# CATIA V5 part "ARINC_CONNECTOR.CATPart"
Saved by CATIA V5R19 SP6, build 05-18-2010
Part number: ARINC_CONNECTOR
Revision: --A
Publications: "Logical Termination.1", "Logical Pin.1", "BCP_A", "Point.3_generated(BCP1)", "Plane.6_generated(BCP1)", "BCP_B", "Point.2_generated(BCP2)", "BCP_C", "Point.1_generated(BCP3)", "CaCP", "Face_generated(CaCP)", "Axis_generated(CaCP)", "Face_generated(CaCP).1", "CCP", "Face_generated(CCP)", "Axis_generated(CCP)", "Face_generated(CCP).1", "InsertFrontFace", "InsertRearFace", "MasterKeywayAxis", "BaCP", "BaCPRPoint_generated(BaCP)", "BaCPCPlane_generated(BaCP)", "Face_generated(BaCP)", "Face_generated(BaCP).1", "Axis_generated(BaCP)"
Bounding box of the stored display mesh (mm): x 0 to 35.56, y -22.86 to 22.86, z -88.646 to 88.646
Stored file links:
  C:\Users\ajc8720\Documents\BOEING_WORK\0001-2CES\004-AP242\Boeing-Generic_Harness_R3\ARINC_CONNECTOR.CATPart
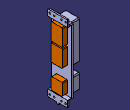
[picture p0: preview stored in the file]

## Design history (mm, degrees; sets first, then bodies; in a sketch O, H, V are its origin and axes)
Parameters
  PartNumber = "ARINC_CONNECTOR"
AxisSystem1 "MasterKeywayAxis": origin (0, 0, 0), X (1, 0, 0), Y (0, 1, 0), Z (0, 0, 1)
Set1 "EGF"
  Set2 "BCP"
    Point1 "BCPRPoint1": type OnSurface, Support start face of Pad4, Length 0, Direction (0, 0.1324, -0.9912)
    Plane1 "BCPPlane": type OffsetPt, RefPlane yz-plane, RefPoint Point1
  Set3 "BCP2"
    Point2 "BCPRPoint2": type OnSurface, Support start face of Pad4, Length 0, Direction (0, 0.4082, -0.9129)
  Set4 "BCP3"
    Point3 "BCPRPoint3": type OnSurface, Support start face of Pad4, Length 0, Direction (0, 0.0589, -0.9983)
  Set5 "CaCP"
    Point4 "CaCPRPoint": (18.923, 0, 0), in AxisSystem1
    Plane2 "CaCPCPlane": type OffsetPt, RefPlane face of Pad1 from Sketch1.L6, RefPoint Point4
  Set6 "CCP"
    Point5 "CCPRPoint": (18.923, 0, 0), in AxisSystem1
  Set7 "BaCP"
    Plane3 "BaCPCPlane": type Offset, RefPlane yz-plane, Offset 24.257
    Point6 "BaCPRPoint": type OnSurface, Support Plane3, Length 0, Direction (0, 0.9983, -0.058)
Set8 "ConstructionGeometry"
  Plane4: type Offset, RefPlane face of Pad1 from Sketch1.L9, Offset 6.35
  Plane5: type Offset, RefPlane xy-plane, Offset 29.21
  Plane6 "DatumCC": type Offset, RefPlane yz-plane, Offset 35.56
  Plane7: type Offset, RefPlane xy-plane, Offset 29.21
  Plane8: type Offset, RefPlane yz-plane, Offset 35.56
Body1 (main body)
  Sketch1 on zx-plane, origin (0, 0, 0), H (-1, 0, 0), V (0, 0, 1)
    line L1 (-24.257, 73.914) -> (-33.274, 73.914)
    line L2 (-33.274, 73.914) -> (-33.274, 88.646)
    line L3 (-33.274, 88.646) -> (-30.099, 88.646)
    line L4 (-30.099, 88.646) -> (-30.099, 76.454)
    line L5 (-30.099, 76.454) -> (-21.082, 76.454)
    line L6 (-21.082, 76.454) -> (-21.082, -72.898)
    line L7 (-21.082, -72.898) -> (-30.099, -72.898)
    point P8 (-30.099, -72.898)
    line L8 (-30.099, -72.898) -> (-30.099, -85.344)
    line L9 (-30.099, -85.344) -> (-33.274, -85.344)
    point P10 (-33.274, -85.344)
    line L10 (-33.274, -85.344) -> (-33.274, -70.358)
    line L11 (-33.274, -70.358) -> (-24.257, -70.358)
    line L12 (-24.257, -70.358) -> (-24.257, 73.914)
    distance L12 L6 = 3.175
    length L9 = 3.175
    distance L6 V = 21.082
    distance L7 L11 = 2.54
    distance L2 V = 33.274
    distance L3 L9 = 173.99
    distance L1 L5 = 2.54
    distance L9 L7 = 12.446
    distance H L9 = 85.344
    distance L9 L5 = 161.798
    horizontal: L1 H, L3 H, L5 H, L7 H, L9 H, L11 H
    vertical: L2 V, L4 V, L6 V, L8 V, L10 V, L12 V
    coincidence: P8 L4, P10 L2
  Pad1: profile Sketch1, direction (0, 1, 0), length 22.86, mirrored extent
  Sketch2 on face of Pad1 from Sketch1.L10, origin (33.274, 0, 0), H (0, 1, 0), V (0, 0, 1)
    point P1 (0, -86.995)
    line L1 (2.3622, -85.344) -> (2.3622, -88.646)
    line L2 (2.3622, -88.646) -> (-2.3622, -88.646)
    line L3 (-2.3622, -88.646) -> (-2.3622, -85.344)
    line L4 (-2.3622, -85.344) -> (2.3622, -85.344)
    reference projected line E1 (-41.402, -85.344) -> (41.402, -85.344) from edge [face of Pad1 from Sketch1.L9 | face of Pad1 from Sketch1.L10]
    length L1 = 3.302
    length L2 = 4.7244
    coincidence: P1 V, L4 E1
    vertical: L1 V, L3 V
    horizontal: L2 H, L4 H
    equidistance: L1 L3 P1, L2 L4 P1
  Pad2: profile Sketch2, direction (-1, 0, 0), length 3.175
  Sketch3 on face of Pad1 from Sketch1.L6, origin (21.082, 0, 0), H (0, -1, 0), V (0, 0, 1)
    point P1 (0, 29.2227)
    line L1 (16.3703, 70.6882) -> (16.3703, -12.2428)
    line L2 (14.2875, -14.3256) -> (-14.2875, -14.3256)
    line L3 (-16.3703, -12.2428) -> (-16.3703, 70.6882)
    line L4 (-14.2875, 72.771) -> (14.2875, 72.771)
    point P2 (0, -52.6923)
    line L5 (16.3703, -37.7952) -> (16.3703, -67.5894)
    line L6 (14.2875, -69.6722) -> (-14.2875, -69.6722)
    line L7 (-16.3703, -67.5894) -> (-16.3703, -37.7952)
    line L8 (-14.2875, -35.7124) -> (14.2875, -35.7124)
    reference projected line E1 (2.3622, -88.646) -> (-2.3622, -88.646) from edge [end face of Pad2 | face of Pad2 from Sketch2.L2]
    arc A1 centre (14.2875, 70.6882) radius 2.0828 from (14.2875, 72.771) to (16.3703, 70.6882) cw
    arc A2 centre (-14.2875, 70.6882) radius 2.0828 from (-14.2875, 72.771) to (-16.3703, 70.6882) ccw
    arc A3 centre (-14.2875, -12.2428) radius 2.0828 from (-16.3703, -12.2428) to (-14.2875, -14.3256) ccw
    arc A4 centre (14.2875, -12.2428) radius 2.0828 from (14.2875, -14.3256) to (16.3703, -12.2428) ccw
    arc A5 centre (14.2875, -37.7952) radius 2.0828 from (14.2875, -35.7124) to (16.3703, -37.7952) cw
    arc A6 centre (-14.2875, -37.7952) radius 2.0828 from (-14.2875, -35.7124) to (-16.3703, -37.7952) ccw
    arc A7 centre (-14.2875, -67.5894) radius 2.0828 from (-16.3703, -67.5894) to (-14.2875, -69.6722) ccw
    arc A8 centre (14.2875, -67.5894) radius 2.0828 from (14.2875, -69.6722) to (16.3703, -67.5894) ccw
    distance P1 P2 = 81.915
    distance L1 L3 = 32.7406
    distance L8 L6 = 33.9598
    distance L2 L4 = 87.0966
    distance E1 L4 = 161.417
    radius A1 = 2.0828
    radius A2 = 2.0828
    radius A3 = 2.0828
    radius A4 = 2.0828
    radius A5 = 2.0828
    radius A6 = 2.0828
    radius A7 = 2.0828
    radius A8 = 2.0828
    coincidence: P1 V, P2 V, L5 L1
    vertical: L1 V, L3 V, L5 V, L7 V
    horizontal: L2 H, L4 H, L6 H, L8 H
    equidistance: L1 L3 P1, L2 L4 P1, L5 L7 P2, L6 L8 P2
    tangency: A1 L4, A1 L1, A2 L4, A2 L3, A3 L3, A3 L2, A4 L2, A4 L1, A5 L8, A5 L5, A6 L8, A6 L7, A7 L7, A7 L6, A8 L6, A8 L5
  Pad3: profile Sketch3, direction (-1, 0, 0), length 21.082
  Sketch4 on end face of Pad3, origin (0, 0, 0), H (0, -1, 0), V (0, 0, 1)
    point P1 (0, -52.705)
    line L1 (13.4239, -40.7289) -> (13.4239, -64.6811)
    line L2 (11.3411, -66.7639) -> (-11.3411, -66.7639)
    line L3 (-13.4239, -64.6811) -> (-13.4239, -40.7289)
    line L4 (-11.3411, -38.6461) -> (11.3411, -38.6461)
    point P2 (0, 8.255)
    line L5 (13.4239, 25.5651) -> (13.4239, -9.0551)
    line L6 (11.3411, -11.1379) -> (-11.3411, -11.1379)
    line L7 (-13.4239, -9.0551) -> (-13.4239, 25.5651)
    line L8 (-11.3411, 27.6479) -> (11.3411, 27.6479)
    point P3 (0, 50.165)
    line L9 (13.4239, 67.4751) -> (13.4239, 32.8549)
    line L10 (11.3411, 30.7721) -> (-11.3411, 30.7721)
    line L11 (-13.4239, 32.8549) -> (-13.4239, 67.4751)
    line L12 (-11.3411, 69.5579) -> (11.3411, 69.5579)
    reference intersected line E1 through (0, 29.21) direction (-1, 0) from Plane7
    reference intersected line E2 through (0, 29.21) direction (-1, 0) from Plane7
    reference intersected line E3 through (0, 29.21) direction (-1, 0) from Plane7
    arc A1 centre (11.3411, 67.4751) radius 2.0828 from (11.3411, 69.5579) to (13.4239, 67.4751) cw
    arc A2 centre (-11.3411, 67.4751) radius 2.0828 from (-11.3411, 69.5579) to (-13.4239, 67.4751) ccw
    arc A3 centre (-11.3411, 32.8549) radius 2.0828 from (-13.4239, 32.8549) to (-11.3411, 30.7721) ccw
    arc A4 centre (11.3411, 32.8549) radius 2.0828 from (11.3411, 30.7721) to (13.4239, 32.8549) ccw
    arc A5 centre (11.3411, 25.5651) radius 2.0828 from (11.3411, 27.6479) to (13.4239, 25.5651) cw
    arc A6 centre (-11.3411, 25.5651) radius 2.0828 from (-11.3411, 27.6479) to (-13.4239, 25.5651) ccw
    arc A7 centre (-11.3411, -9.0551) radius 2.0828 from (-13.4239, -9.0551) to (-11.3411, -11.1379) ccw
    arc A8 centre (11.3411, -9.0551) radius 2.0828 from (11.3411, -11.1379) to (13.4239, -9.0551) ccw
    arc A9 centre (11.3411, -40.7289) radius 2.0828 from (11.3411, -38.6461) to (13.4239, -40.7289) cw
    arc A10 centre (-11.3411, -40.7289) radius 2.0828 from (-11.3411, -38.6461) to (-13.4239, -40.7289) ccw
    arc A11 centre (-11.3411, -64.6811) radius 2.0828 from (-13.4239, -64.6811) to (-11.3411, -66.7639) ccw
    arc A12 centre (11.3411, -64.6811) radius 2.0828 from (11.3411, -66.7639) to (13.4239, -64.6811) ccw
    distance L3 L1 = 26.8478
    distance L2 L4 = 28.1178
    distance L6 L8 = 38.7858
    distance L10 L12 = 38.7858
    distance P3 E1 = 20.955
    distance P2 E2 = 20.955
    distance E3 P1 = 81.915
    radius A1 = 2.0828
    radius A2 = 2.0828
    radius A3 = 2.0828
    radius A4 = 2.0828
    radius A5 = 2.0828
    radius A6 = 2.0828
    radius A7 = 2.0828
    radius A8 = 2.0828
    radius A9 = 2.0828
    radius A10 = 2.0828
    radius A11 = 2.0828
    radius A12 = 2.0828
    distance L9 L11 = 26.8478
    coincidence: P1 V, P2 V, P3 V, L5 L9
    vertical: L1 V, L3 V, L5 V, L7 V, L9 V, L11 V
    horizontal: L2 H, L4 H, L6 H, L8 H, L10 H, L12 H
    equidistance: L1 L3 P1, L2 L4 P1, L5 L7 P2, L6 L8 P2, L9 L11 P3, L10 L12 P3
    tangency: A1 L12, A1 L9, A2 L12, A2 L11, A3 L11, A3 L10, A4 L10, A4 L9, A5 L8, A5 L5, A6 L8, A6 L7, A7 L7, A7 L6, A8 L6, A8 L5, A9 L4, A9 L1, A10 L4, A10 L3, A11 L3, A11 L2, A12 L2, A12 L1
  Pocket1: profile Sketch4, direction (1, 0, 0), through (limit type 3)
  Fillet1: radius 1.5748, on edge [face of Pad1 from Sketch1.L9 | end face of Pad1]; edge [start face of Pad1 | face of Pad1 from Sketch1.L9]; edge [start face of Pad1 | face of Pad1 from Sketch1.L3]; edge [face of Pad1 from Sketch1.L3 | end face of Pad1]; edge [face of Pad1 from Sketch1.L5 | end face of Pad1]; edge [start face of Pad1 | face of Pad1 from Sketch1.L5]; edge [start face of Pad1 | face of Pad1 from Sketch1.L7]; edge [face of Pad1 from Sketch1.L7 | end face of Pad1]
  Sketch5 on face of Pad2, origin (30.099, 0, 0), H (0, -1, 0), V (0, 0, 1)
    point P1 (-13.2754, -80.645)
    circle A1 centre (-8.255, -78.994) radius 1.8796
    point P2 (-8.255, -78.994)
    point P3 (8.255, -78.994)
    circle A2 centre (8.255, -78.994) radius 1.8796
    reference intersected line E1 through (0, -78.994) direction (-1, 0) from Plane4
    radius A1 = 1.8796
    distance V P2 = 8.255
    symmetry: A1 A2 V
    coincidence: P3 E1
  Pocket2: profile Sketch5, direction (-1, 0, 0), through (limit type 6)
  RectPattern1: of Pocket2, direction 1 instances 2, spacing 161.29, along Z axis
  Sketch6 on face of Pad2, origin (33.274, 0, 0), H (0, 1, 0), V (0, 0, 1)
    circle A1 centre (-18.1102, -78.994) radius 1.8796
    point P1 (-18.1102, -78.994)
    circle A2 centre (18.1102, -78.994) radius 1.8796
    point P2 (18.1102, -78.994)
    reference intersected line E1 through (0, -78.994) direction (-1, 0) from Plane4
    distance P1 P2 = 36.2204
    radius A2 = 1.8796
    radius A1 = 1.8796
    symmetry: P2 P1 V
    coincidence: P2 E1
  Pocket3: profile Sketch6, direction (-1, 0, 0), through (limit type 6)
  RectPattern2: of Pocket3, direction 1 instances 2, spacing 161.29, along Z axis
Body2 "Insert"
  Sketch7 "Sketch.12.Renamed" on Plane8, origin (35.56, 0, 0), H (0, 1, 0), V (0, 0, 1)
    line L1 (13.1699, -40.386) -> (13.1699, -65.024)
    line L2 (11.6459, -66.548) -> (-11.6459, -66.548)
    line L3 (-13.1699, -65.024) -> (-13.1699, -40.386)
    line L4 (-11.6459, -38.862) -> (11.6459, -38.862)
    point P1 (0, -52.705)
    point P2 (13.1699, -38.862)
    point P3 (13.1699, -66.548)
    point P4 (-13.1699, -66.548)
    reference intersected line E1 through (0, 29.21) direction (-1, 0) from Plane5
    arc A1 centre (11.6459, -40.386) radius 1.524 from (11.6459, -38.862) to (13.1699, -40.386) cw
    arc A2 centre (-11.6459, -40.386) radius 1.524 from (-13.1699, -40.386) to (-11.6459, -38.862) cw
    arc A3 centre (-11.6459, -65.024) radius 1.524 from (-13.1699, -65.024) to (-11.6459, -66.548) ccw
    arc A4 centre (11.6459, -65.024) radius 1.524 from (11.6459, -66.548) to (13.1699, -65.024) ccw
    construction line L5 through (0, 0) direction (0, 1)
    line L6 (13.1699, 68.072) -> (13.1699, 32.258)
    construction line L7 through (-10.9657, 4683.093) direction (1, 0)
    line L8 (11.6459, 30.734) -> (-11.6459, 30.734)
    line L9 (-13.1699, 32.258) -> (-13.1699, 68.072)
    line L10 (-11.6459, 69.596) -> (11.6459, 69.596)
    point P17 (0, 50.165)
    line L11 (13.1699, 26.162) -> (13.1699, -9.652)
    line L12 (11.6459, -11.176) -> (-11.6459, -11.176)
    line L13 (-13.1699, -9.652) -> (-13.1699, 26.162)
    line L14 (-11.6459, 27.686) -> (11.6459, 27.686)
    point P18 (0, 8.255)
    point P19 (13.1699, 27.686)
    point P20 (13.1699, 69.596)
    arc A5 centre (11.6459, 68.072) radius 1.524 from (11.6459, 69.596) to (13.1699, 68.072) cw
    arc A6 centre (-11.6459, 68.072) radius 1.524 from (-13.1699, 68.072) to (-11.6459, 69.596) cw
    arc A7 centre (-11.6459, 32.258) radius 1.524 from (-13.1699, 32.258) to (-11.6459, 30.734) ccw
    point P21 (13.1699, 30.734)
    arc A8 centre (11.6459, 32.258) radius 1.524 from (11.6459, 30.734) to (13.1699, 32.258) ccw
    arc A9 centre (11.6459, 26.162) radius 1.524 from (11.6459, 27.686) to (13.1699, 26.162) cw
    arc A10 centre (-11.6459, 26.162) radius 1.524 from (-13.1699, 26.162) to (-11.6459, 27.686) cw
    arc A11 centre (-11.6459, -9.652) radius 1.524 from (-13.1699, -9.652) to (-11.6459, -11.176) ccw
    point P22 (13.1699, -11.176)
    arc A12 centre (11.6459, -9.652) radius 1.524 from (11.6459, -11.176) to (13.1699, -9.652) ccw
    point P23 (0, 0)
    reference intersected line E2 through (0, 29.21) direction (-1, 0) from Plane7
    reference intersected line E3 through (0, 29.21) direction (-1, 0) from Plane7
    distance E1 P1 = 81.915
    distance P2 P3 = 27.686
    radius A1 = 1.524
    radius A2 = 1.524
    distance P3 P4 = 26.3398
    radius A3 = 1.524
    radius A4 = 1.524
    radius A5 = 1.524
    radius A6 = 1.524
    radius A7 = 1.524
    radius A8 = 1.524
    radius A9 = 1.524
    radius A10 = 1.524
    radius A11 = 1.524
    radius A12 = 1.524
    distance E2 P17 = 20.955
    distance L13 L11 = 26.3398
    distance L12 L14 = 38.862
    distance L8 L10 = 38.862
    vertical: L1 V, L3 V, L6 L5, L9 L5, L11 L5, L13 L5
    horizontal: L2 H, L4 H, L8 L7, L10 L7, L12 L7, L14 L7, L12 H, L8 H
    equidistance: L1 L3 P1, L2 L4 P1, L6 L9 P17, L8 L10 P17, L11 L13 P18, L12 L14 P18
    coincidence: L4 P2, L1 P2, L3 P4, L2 P4, L2 P3, L1 P3, P1 V, P19 L6, L6 L11, L13 L9, L10 P20, L6 P20, L8 P21, L6 P21, L14 P19, L11 P19, L12 P22, L11 P22, P17 L5, L5 V
    tangency: A1 L4, A1 L1, A2 L3, A2 L4, A3 L3, A3 L2, A4 L2, A4 L1, A5 L10, A5 L6, A6 L9, A6 L10, A7 L9, A7 L8, A8 L8, A8 L6, A9 L14, A9 L11, A10 L13, A10 L14, A11 L13, A11 L12, A12 L12, A12 L11
    symmetry: P17 P18 E3
  Pad4: profile Sketch7, direction (-1, 0, 0), length 32.766
Body3 "BaCP"
  Sketch8 "Sketch.15" on Plane3, origin (24.257, 0, 0), H (0, 1, 0), V (0, 0, 1)
    circle A1 centre (0, 0) radius 1.27
    point P1 (0, 0)
    reference projected point E1 (0, 0) from Point6
    radius A1 = 1.27
    coincidence: P1 E1
  Pad5: profile Sketch8, direction (1, 0, 0), length 0.254, opposite side length 0.254
  Sketch9 "Sketch.16" on Plane3, origin (24.257, 0, 0), H (0, 1, 0), V (0, 0, 1)
    line L1 (-0.672, 0.762) -> (0.672, 0.762)
    point P1 (-0.672, 0.762)
    point P2 (0.672, 0.762)
    arc A1 centre (0, 0) radius 1.016 from (-1.016, 0) to (1.016, 0) ccw
    point P3 (0, 0)
    point P4 (-1.016, 0)
    point P5 (1.016, 0)
    reference projected point E1 (0, 0) from Point6
    arc A2 centre (0, 0) radius 1.016 from (1.016, 0) to (0.672, 0.762) ccw
    point P6 (0, 0)
    point P7 (1.016, 0)
    point P8 (0.672, 0.762)
    arc A3 centre (0, 0) radius 1.016 from (-0.672, 0.762) to (-1.016, 0) ccw
    point P9 (0, 0)
    point P10 (-0.672, 0.762)
    point P11 (-1.016, 0)
    reference projected point E2 (0, 0) from Point6
    reference projected point E3 (0, 0) from Point6
    length L1 = 1.344
    radius A1 = 1.016
    radius A3 = 1.016
    radius A2 = 1.016
    distance L1 P5 = 0.762
    distance P4 L1 = 0.762
    distance P7 L1 = 0.762
    distance P11 L1 = 0.762
    coincidence: P3 E1, P6 E2, P9 E3, P8 P2, P10 P1
    horizontal: L1 H
  Pocket4: profile Sketch9, direction (1, 0, 0), through (limit type 6)
Body4 "CaCP"
  Sketch10 on Plane2, origin (18.923, 0, 0), H (0, 1, 0), V (0, 0, 1)
    arc A1 centre (0, 0) radius 1.016 from (-0.672, 0.762) to (0.672, 0.762) ccw
    line L1 (-0.672, 0.762) -> (0.672, 0.762)
    distance L1 H = 0.762
    radius A1 = 1.016
  Pad6: profile Sketch10, direction (1, 0, 0), length 0.508
Body5 "CCP"
  Sketch11 on Plane2, origin (18.923, 0, 0), H (0, 1, 0), V (0, 0, 1)
    arc A1 centre (0, 0) radius 1.016 from (-0.672, 0.762) to (0.672, 0.762) ccw
    line L1 (-0.672, 0.762) -> (0.672, 0.762)
    distance L1 H = 0.762
    radius A1 = 1.016
  Pad7: profile Sketch11, direction (1, 0, 0), length 0.508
